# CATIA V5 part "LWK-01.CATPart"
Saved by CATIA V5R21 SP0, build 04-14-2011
Part number: LWK-01.SLDPRT
Bounding box of the stored display mesh (mm): x -1.362 to 1.338, y -0.976 to 1.024, z 2.1 to 2.7
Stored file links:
  C:\Users\user\Desktop\CATIA文件\0-最新文件\LWK-01\LWK-01.CATPart
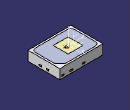
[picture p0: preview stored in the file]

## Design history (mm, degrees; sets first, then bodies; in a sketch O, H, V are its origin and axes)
AxisSystem1: origin (-0.1815, 0.0244, 2.7), X (0, 1, 0), Y (-1, 0, 0), Z (0, 0, 1)
Set1
  DatumSurface1 to DatumSurface42
  Line1: stored without definition
  Circle1: stored without definition
  Line2: stored without definition
  Circle2: stored without definition
  Line3: stored without definition
  Circle3: stored without definition
  Line4: stored without definition
  Circle4: stored without definition
  Line5: stored without definition
  Circle5: stored without definition
  Line6: stored without definition
  Circle6: stored without definition
  Line7: stored without definition
  Circle7: stored without definition
  Line8: stored without definition
  Line9: stored without definition
  Circle8: stored without definition
  Line10: stored without definition
  Line11: stored without definition
  Circle9: stored without definition
  Line12: stored without definition
  Line13: stored without definition
  Circle10: stored without definition
  Line14 to Line18: stored without definition
  Circle11: stored without definition
  Line19: stored without definition
  Circle12: stored without definition
  Line20: stored without definition
  Circle13: stored without definition
  Line21: stored without definition
  Circle14: stored without definition
  Line22: stored without definition
  Circle15: stored without definition
  Line23: stored without definition
  Circle16: stored without definition
  Line24: stored without definition
  Circle17: stored without definition
  Line25: stored without definition
  Circle18: stored without definition
  Line26: stored without definition
  Circle19: stored without definition
  Line27: stored without definition
  Circle20: stored without definition
  Line28 to Line30: stored without definition
  Circle21: stored without definition
  Line31: stored without definition
  Circle22: stored without definition
  Line32: stored without definition
  Circle23: stored without definition
  Line33: stored without definition
  Circle24: stored without definition
  Line34: stored without definition
  Line35: stored without definition
  Circle25: stored without definition
  Line36: stored without definition
  Circle26: stored without definition
  Line37: stored without definition
  Circle27: stored without definition
  Line38: stored without definition
  Circle28: stored without definition
  Line39: stored without definition
  Circle29: stored without definition
  Line40: stored without definition
  Circle30: stored without definition
  Line41: stored without definition
  Circle31: stored without definition
  Line42: stored without definition
  Circle32: stored without definition
  Line43: stored without definition
  Circle33: stored without definition
  Line44 to Line46: stored without definition
  Circle34: stored without definition
  Line47: stored without definition
  Circle35: stored without definition
  Line48: stored without definition
  Circle36: stored without definition
  Line49: stored without definition
  Circle37: stored without definition
  Line50: stored without definition
  Circle38: stored without definition
  Line51 to Line79: stored without definition
  DatumSurface43 to DatumSurface79
  Line80: stored without definition
  Circle39: stored without definition
  Line81: stored without definition
  Circle40: stored without definition
  Line82: stored without definition
  Circle41: stored without definition
  Line83: stored without definition
  Circle42: stored without definition
  Circle43: stored without definition
  Line84 to Line87: stored without definition
  Circle44: stored without definition
  Line88 to Line90: stored without definition
  Circle45: stored without definition
  Line91 to Line93: stored without definition
  Circle46: stored without definition
  Line94: stored without definition
  Line95: stored without definition
  Circle47: stored without definition
  Line96: stored without definition
  Circle48: stored without definition
  Line97: stored without definition
  Circle49: stored without definition
  Line98 to Line100: stored without definition
  Circle50: stored without definition
  Line101: stored without definition
  Circle51: stored without definition
  Line102: stored without definition
  Circle52: stored without definition
  Line103: stored without definition
  Circle53: stored without definition
  Line104: stored without definition
  Circle54: stored without definition
  Line105 to Line107: stored without definition
  Circle55: stored without definition
  Line108: stored without definition
  Circle56: stored without definition
  Line109 to Line112: stored without definition
  Circle57: stored without definition
  Line113: stored without definition
  Circle58: stored without definition
  Line114: stored without definition
  Circle59: stored without definition
  Line115 to Line117: stored without definition
  Circle60: stored without definition
  Line118: stored without definition
  Circle61: stored without definition
  Line119: stored without definition
  Circle62: stored without definition
  Line120: stored without definition
  Circle63: stored without definition
  Line121: stored without definition
  Circle64: stored without definition
  Line122 to Line124: stored without definition
  Circle65: stored without definition
  Line125: stored without definition
  Circle66: stored without definition
  Line126 to Line153: stored without definition
  DatumSurface80 to DatumSurface154
  DatumCurve1
  DatumCurve2
  Circle67: stored without definition
  Line154: stored without definition
  Circle68: stored without definition
  Line155: stored without definition
  Line156: stored without definition
  Circle69: stored without definition
  Line157: stored without definition
  Circle70: stored without definition
  Line158 to Line160: stored without definition
  Circle71: stored without definition
  Line161: stored without definition
  Circle72: stored without definition
  Line162 to Line164: stored without definition
  Circle73: stored without definition
  Line165: stored without definition
  Circle74: stored without definition
  Line166 to Line168: stored without definition
  Circle75: stored without definition
  Line169: stored without definition
  Circle76: stored without definition
  Line170: stored without definition
  Line171: stored without definition
  Circle77: stored without definition
  Line172: stored without definition
  Circle78: stored without definition
  Line173: stored without definition
  Circle79: stored without definition
  Line174 to Line176: stored without definition
  Circle80: stored without definition
  Line177: stored without definition
  Circle81: stored without definition
  Line178: stored without definition
  Circle82: stored without definition
  Line179: stored without definition
  Circle83: stored without definition
  Line180: stored without definition
  Circle84: stored without definition
  Line181 to Line183: stored without definition
  Circle85: stored without definition
  Line184: stored without definition
  Circle86: stored without definition
  Line185 to Line187: stored without definition
  Circle87: stored without definition
  Line188: stored without definition
  Line189: stored without definition
  Circle88: stored without definition
  Line190: stored without definition
  Line191: stored without definition
  Circle89: stored without definition
  Line192 to Line198: stored without definition
  Circle90: stored without definition
  Line199 to Line202: stored without definition
  Circle91: stored without definition
  Line203: stored without definition
  Line204: stored without definition
  Circle92: stored without definition
  Line205 to Line208: stored without definition
  Circle93: stored without definition
  Line209: stored without definition
  Line210: stored without definition
  Circle94: stored without definition
  Line211 to Line216: stored without definition
  Circle95: stored without definition
  Line217 to Line219: stored without definition
  Circle96: stored without definition
  Line220 to Line229: stored without definition
  Circle97: stored without definition
  Line230: stored without definition
  Circle98: stored without definition
  Line231: stored without definition
  Circle99: stored without definition
  Line232: stored without definition
  Circle100: stored without definition
  Line233: stored without definition
  Circle101: stored without definition
  Line234: stored without definition
  Circle102: stored without definition
  Line235: stored without definition
  Circle103: stored without definition
  Line236: stored without definition
  Circle104: stored without definition
  Line237 to Line245: stored without definition
  Circle105: stored without definition
  Line246: stored without definition
  Circle106: stored without definition
  Line247: stored without definition
  Circle107: stored without definition
  Line248: stored without definition
  Circle108: stored without definition
  Line249: stored without definition
  Circle109: stored without definition
  Line250: stored without definition
  Circle110: stored without definition
  Line251: stored without definition
  Circle111: stored without definition
  Line252: stored without definition
  Circle112: stored without definition
  Line253: stored without definition
  Circle113: stored without definition
  Line254: stored without definition
  Circle114: stored without definition
  Line255: stored without definition
  Circle115: stored without definition
  Line256: stored without definition
  Circle116: stored without definition
  Line257: stored without definition
  Circle117: stored without definition
  Line258 to Line260: stored without definition
  Circle118: stored without definition
  Line261: stored without definition
  Circle119: stored without definition
  Line262: stored without definition
  Circle120: stored without definition
  Line263: stored without definition
  Circle121: stored without definition
  Line264: stored without definition
  Circle122: stored without definition
  Line265: stored without definition
  Circle123: stored without definition
  Line266: stored without definition
  Circle124: stored without definition
  Line267: stored without definition
  Circle125: stored without definition
  Line268: stored without definition
  Circle126: stored without definition
  Line269: stored without definition
  Circle127: stored without definition
  Line270: stored without definition
  Circle128: stored without definition
  Line271 to Line273: stored without definition
  Circle129: stored without definition
  Line274: stored without definition
  Circle130: stored without definition
  Line275: stored without definition
  Circle131: stored without definition
  Line276: stored without definition
  Circle132: stored without definition
  Line277 to Line313: stored without definition
  DatumCurve3
  Line314: stored without definition
  DatumCurve4
  Line315: stored without definition
  DatumCurve5
  Line316: stored without definition
  DatumCurve6
  Line317: stored without definition
  DatumCurve7
  Line318 to Line323: stored without definition
  DatumCurve8
  Line324: stored without definition
  DatumCurve9
  Line325: stored without definition
  DatumCurve10
  Line326: stored without definition
  DatumCurve11
  Line327: stored without definition
  DatumCurve12
  Line328 to Line336: stored without definition
  Point1 "几何中心": type Between, FirstPoint vertex [face of DatumSurface148], SecondPoint vertex [face of DatumSurface147], Ratio 0.5
  Point2 "发光中心（测试原点）": type Between, FirstPoint vertex [face of DatumSurface154], SecondPoint vertex [face of DatumSurface154], Ratio 0.5
  Point3 "虚拟坐标": (-0.0028, -0.0311, -0.1047), relative to Point2, in AxisSystem1
Body1 (main body)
